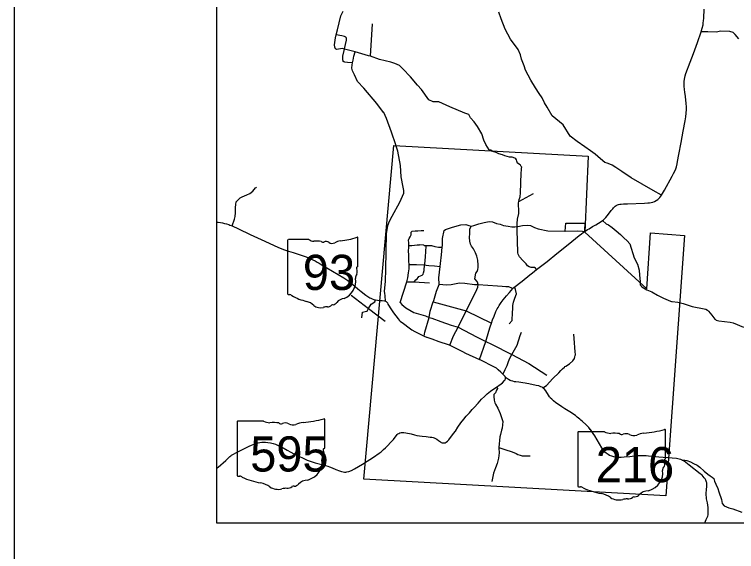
# Model space of a CAD drawing. Extents: x 2025369 to 2161369, y 549489 to 637489.
# Drawn here: x 2033369 to 2047673, y 570995 to 581630 of the extents above; entities that cross this region are included whole.
import ezdxf

# ---------------------------------------------------------------- set-up
doc = ezdxf.new("R2010")
doc.units = 0
for name, color, linetype in [('GM_X_City_Street', 7, 'Continuous'), ('GM_X_Corporation', 7, 'Continuous'), ('GM_X_County_Road', 7, 'Continuous'), ('GM_X_State_Route', 7, 'Continuous'), ('GM_X_State_Shield', 7, 'Continuous'), ('GM_X_Township_Road', 7, 'Continuous'), ('GM_X_Township_Subdivision', 7, 'Continuous'), ('SH_Border', 7, 'Continuous'), ('SH_Text', 7, 'Continuous')]:
    doc.layers.add(name, color=color, linetype=linetype)

msp = doc.modelspace()

# ---------------------------------------------------------------- linework, layer by layer
at = {"layer": 'GM_X_City_Street'}
for points in [[(2040772, 577465), (2040790, 577527), (2040851, 577634), (2041000, 577910), (2041058, 578035), (2041079, 578089), (2041079, 578141), (2041070, 578209), (2041026, 578413), (2041013, 578639), (2040960, 578922), (2040925, 579042), (2040923, 579047), (2040922, 579049)], [(2043343, 576907), (2043341, 576925), (2043327, 577359), (2043328, 577430), (2043328, 577489), (2043336, 577576), (2043358, 577688), (2043358, 577776), (2043356, 577842), (2043355, 577898), (2043360, 577926), (2043366, 577963), (2043383, 578017), (2043395, 578097), (2043404, 578490), (2043413, 578556), (2043414, 578586), (2043416, 578608), (2043409, 578622), (2043391, 578644), (2043373, 578658), (2043348, 578677), (2043332, 578685), (2043317, 578724), (2043313, 578750), (2043302, 578772), (2043278, 578782), (2043227, 578804), (2043173, 578807), (2043083, 578831), (2043036, 578852), (2042962, 578873), (2042914, 578896), (2042847, 578915)], [(2043360, 577926), (2043649, 578087)], [(2041878, 577355), (2041908, 577372), (2042043, 577421), (2042210, 577462), (2042311, 577469), (2042370, 577454), (2042418, 577437), (2042466, 577448), (2042569, 577484), (2042670, 577509), (2042770, 577531), (2042840, 577525), (2042918, 577494), (2042993, 577476), (2043059, 577453), (2043147, 577437), (2043222, 577427), (2043278, 577426), (2043328, 577430), (2043341, 577432), (2043431, 577450), (2043525, 577456), (2043593, 577453), (2043668, 577411), (2043746, 577385), (2043931, 577347), (2044273, 577336), (2044277, 577336), (2044520, 577345), (2044622, 577337), (2044663, 577332)], [(2044277, 577336), (2044293, 577497)], [(2044293, 577497), (2044675, 577499)], [(2044663, 577332), (2044664, 577357), (2044675, 577499)], [(2041178, 577002), (2041183, 577055), (2041180, 577107), (2041175, 577161), (2041178, 577181), (2041186, 577192), (2041207, 577226), (2041225, 577264), (2041228, 577298), (2041229, 577322), (2041247, 577337), (2041305, 577344), (2041359, 577347), (2041422, 577351), (2041476, 577350)], [(2041810, 576697), (2041831, 576871), (2041844, 577023), (2041847, 577052), (2041850, 577192), (2041878, 577355)], [(2042539, 576326), (2042534, 576343), (2042485, 576395), (2042510, 576506), (2042535, 576543), (2042549, 576581), (2042554, 576621), (2042551, 576667), (2042545, 576765), (2042529, 576843), (2042499, 576912), (2042460, 576991), (2042423, 577045), (2042404, 577080), (2042386, 577144), (2042383, 577212), (2042391, 577296), (2042392, 577338), (2042387, 577378), (2042418, 577437)], [(2041183, 577055), (2041243, 577056), (2041347, 577069), (2041380, 577071)], [(2041285, 576333), (2041293, 576343), (2041322, 576375), (2041347, 576398), (2041367, 576421), (2041382, 576439), (2041410, 576452), (2041446, 576470), (2041465, 576489), (2041471, 576513), (2041484, 576563), (2041494, 576674), (2041495, 576684), (2041514, 576830), (2041525, 577043), (2041525, 577057)], [(2041380, 577071), (2041389, 577071), (2041395, 577072), (2041469, 577069), (2041487, 577058), (2041519, 577057), (2041525, 577057), (2041583, 577056), (2041629, 577057), (2041697, 577035), (2041770, 577020), (2041844, 577023)], [(2041141, 576339), (2041161, 576412), (2041171, 576514), (2041185, 576593), (2041188, 576671), (2041187, 576681), (2041182, 576745), (2041178, 576851), (2041175, 576965), (2041178, 577002)], [(2043713, 576582), (2043689, 576607), (2043668, 576618), (2043637, 576618), (2043601, 576621), (2043564, 576635), (2043532, 576651), (2043503, 576691), (2043437, 576759), (2043373, 576834), (2043346, 576884), (2043343, 576907)], [(2041187, 576681), (2041331, 576680), (2041487, 576675), (2041494, 576674)], [(2041484, 575261), (2041499, 575338), (2041584, 575632), (2041601, 575755), (2041663, 575941), (2041673, 575969), (2041729, 576150), (2041780, 576284), (2041779, 576292), (2041777, 576414), (2041804, 576642), (2041810, 576697)], [(2041494, 576674), (2041521, 576669), (2041578, 576657), (2041688, 576650), (2041804, 576642)], [(2041008, 575926), (2041141, 576339)], [(2041141, 576339), (2041285, 576333), (2041591, 576319)], [(2041779, 576292), (2041852, 576281), (2041918, 576279), (2042021, 576283), (2042187, 576318), (2042293, 576307), (2042484, 576281), (2042553, 576280), (2042936, 576258), (2043028, 576251), (2043101, 576242), (2043157, 576241), (2043213, 576219), (2043241, 576202)], [(2041991, 575083), (2042068, 575265), (2042155, 575439), (2042319, 575764), (2042506, 576139), (2042546, 576228), (2042553, 576280), (2042539, 576326)], [(2043168, 575506), (2043227, 575569), (2043235, 575731), (2043239, 575799), (2043244, 575866), (2043256, 575935), (2043281, 576011), (2043311, 576101), (2043294, 576181), (2043284, 576202), (2043264, 576222)], [(2045780, 576257), (2045784, 576250), (2045793, 576236), (2045897, 576175), (2045996, 576135), (2046106, 576070), (2046223, 576013), (2046367, 575951), (2046387, 575949)], [(2040719, 575954), (2040710, 576060), (2040705, 576110)], [(2041008, 575926), (2041039, 575885), (2041122, 575824), (2041278, 575730), (2041510, 575662), (2041584, 575632), (2041636, 575614)], [(2041663, 575941), (2042319, 575764), (2042817, 575515)], [(2041636, 575614), (2041816, 575549), (2042018, 575475), (2042155, 575439), (2042521, 575248)], [(2043129, 574681), (2043146, 574741), (2043175, 574812), (2043224, 574900), (2043324, 575079), (2043387, 575272), (2043413, 575341)], [(2042521, 575248), (2042703, 575152)], [(2044479, 574898), (2044473, 574952), (2044453, 575212), (2044451, 575300)], [(2042703, 575152), (2042817, 575103), (2043224, 574900), (2043558, 574722), (2043915, 574489)], [(2044290, 574669), (2044362, 574714), (2044429, 574771), (2044464, 574818), (2044471, 574852), (2044478, 574879), (2044480, 574888), (2044479, 574898)], [(2043043, 574510), (2043076, 574570), (2043087, 574597), (2043124, 574665), (2043129, 574681)], [(2043837, 574240), (2043907, 574285), (2044033, 574420), (2044154, 574535), (2044193, 574580), (2044228, 574615), (2044262, 574648), (2044271, 574658), (2044290, 574669)], [(2042927, 574258), (2042936, 574224), (2042916, 574188), (2042895, 574135), (2042866, 574104), (2042863, 574086), (2042863, 574064), (2042871, 573996), (2042876, 573968), (2042887, 573937), (2042899, 573913), (2042942, 573835), (2042990, 573728), (2043040, 573573), (2043029, 573441), (2043017, 573397), (2042995, 573316)], [(2042995, 573316), (2042981, 573265), (2042966, 573054), (2042966, 573043), (2042970, 572953), (2042954, 572846), (2042932, 572742), (2042898, 572653), (2042857, 572548), (2042835, 572447), (2042826, 572381)], [(2042966, 573054), (2043084, 573019), (2043227, 572971), (2043304, 572936), (2043340, 572917), (2043383, 572902), (2043425, 572893), (2043493, 572888), (2043539, 572889), (2043585, 572892)]]:
    msp.add_lwpolyline(points, dxfattribs=at)
at = {"layer": 'GM_X_Corporation'}
msp.add_lwpolyline([(2044730, 578821), (2044666, 577321), (2045892, 576198), (2045966, 577309), (2046644, 577256), (2046273, 572097), (2040289, 572431), (2040884, 579034)], close=True, dxfattribs=at)
at = {"layer": 'GM_X_County_Road'}
for points in [[(2040686, 579686), (2040686, 579687), (2040682, 579691), (2040550, 579866), (2040292, 580173), (2040163, 580301), (2040102, 580437), (2040067, 580514), (2040052, 580564), (2040059, 580630), (2040068, 580671), (2040078, 580724), (2040091, 580803), (2040118, 580889), (2039908, 580945), (2039860, 580958), (2039752, 580933), (2039726, 580948), (2039712, 580980), (2039709, 581030), (2039728, 581164), (2039742, 581224), (2039766, 581327), (2039837, 581600), (2039877, 581697)], [(2047717, 581148), (2047648, 581236), (2047605, 581274), (2047542, 581292), (2047364, 581302), (2047268, 581282), (2047102, 581283), (2046973, 581288)], [(2040922, 579049), (2040838, 579301), (2040739, 579568), (2040686, 579686)], [(2040705, 576110), (2040702, 576145), (2040717, 576346), (2040724, 576586), (2040741, 577295), (2040765, 577443), (2040768, 577453), (2040772, 577465)], [(2045018, 577549), (2045092, 577484), (2045134, 577467), (2045211, 577412), (2045289, 577346), (2045374, 577272), (2045441, 577205), (2045505, 577149), (2045560, 577089), (2045646, 576813), (2045712, 576683), (2045741, 576568), (2045752, 576470), (2045762, 576340), (2045766, 576278), (2045780, 576257)], [(2046387, 575949), (2046394, 575948), (2046510, 575933), (2046612, 575910), (2046794, 575848), (2047031, 575803), (2047065, 575792), (2047095, 575775), (2047117, 575752), (2047186, 575675), (2047242, 575599), (2047255, 575587), (2047271, 575576), (2047323, 575562), (2047545, 575535), (2047606, 575523), (2047810, 575441)]]:
    msp.add_lwpolyline(points, dxfattribs=at)
at = {"layer": 'GM_X_State_Route'}
for points in [[(2044663, 577332), (2044693, 577353), (2044720, 577370), (2044752, 577388), (2044822, 577429), (2044886, 577466), (2044935, 577495), (2044992, 577530), (2045018, 577549), (2045039, 577566), (2045059, 577585), (2045084, 577612), (2045133, 577673), (2045192, 577750), (2045219, 577784), (2045234, 577801), (2045248, 577815), (2045268, 577831), (2045290, 577845), (2045314, 577858), (2045336, 577867), (2045359, 577871), (2045390, 577876), (2045430, 577879), (2045512, 577882), (2045850, 577895), (2045916, 577897), (2045949, 577900), (2045982, 577905), (2046015, 577912), (2046050, 577926), (2046083, 577944), (2046115, 577967), (2046150, 578004), (2046171, 578032), (2046185, 578053), (2046242, 578151), (2046397, 578425), (2046425, 578478), (2046449, 578524), (2046468, 578572), (2046482, 578615), (2046496, 578671), (2046505, 578716), (2046532, 578860), (2046575, 579095), (2046616, 579316), (2046655, 579527), (2046667, 579605), (2046676, 579675), (2046681, 579750), (2046679, 579803), (2046675, 579869), (2046661, 580003), (2046649, 580090), (2046643, 580144), (2046636, 580211), (2046633, 580255), (2046634, 580301), (2046640, 580348), (2046646, 580382), (2046655, 580415), (2046669, 580460), (2046753, 580683), (2046819, 580860), (2046896, 581074), (2046973, 581288), (2046993, 581359), (2047008, 581423), (2047014, 581464), (2047019, 581505), (2047023, 581558), (2047031, 581736)], [(2037369, 577517), (2037403, 577515), (2037449, 577510), (2037491, 577504), (2037531, 577493), (2037572, 577482), (2037615, 577468), (2037635, 577461), (2037679, 577444), (2037805, 577383), (2038037, 577271), (2038256, 577171), (2038588, 577022), (2038701, 576978), (2038798, 576943), (2038888, 576915), (2038969, 576889), (2039148, 576828), (2039192, 576811), (2039238, 576793), (2039280, 576774), (2039327, 576749), (2039365, 576728), (2039407, 576704), (2039446, 576681), (2039894, 576415), (2039970, 576364), (2039999, 576345), (2040021, 576329), (2040173, 576199)], [(2043632, 576516), (2043713, 576582), (2043918, 576740), (2044115, 576899), (2044338, 577077), (2044558, 577254), (2044604, 577289), (2044634, 577312), (2044663, 577332)], [(2042956, 575843), (2042972, 575870), (2043009, 575926), (2043047, 575979), (2043115, 576061), (2043173, 576126), (2043241, 576202), (2043264, 576222), (2043423, 576347), (2043580, 576474), (2043632, 576516)], [(2040173, 576199), (2040238, 576144), (2040331, 576072), (2040366, 576047), (2040387, 576033), (2040408, 576021), (2040430, 576011), (2040457, 576000), (2040487, 575989), (2040521, 575980), (2040560, 575971), (2040598, 575967), (2040652, 575964), (2040653, 575964)], [(2040653, 575964), (2040701, 575960), (2040719, 575954), (2040733, 575945), (2040744, 575934), (2040755, 575918), (2040767, 575896), (2040778, 575874), (2040822, 575798), (2040848, 575759), (2040876, 575722), (2040969, 575603), (2040989, 575580), (2041009, 575560), (2041073, 575508), (2041190, 575422), (2041241, 575387), (2041301, 575354), (2041354, 575327), (2041484, 575261), (2041533, 575240)], [(2042869, 575659), (2042904, 575746), (2042931, 575801), (2042948, 575830), (2042956, 575843)], [(2042768, 575360), (2042793, 575442), (2042817, 575515), (2042840, 575584), (2042869, 575659), (2042869, 575659)], [(2042578, 574797), (2042703, 575152), (2042768, 575360)], [(2041533, 575240), (2041540, 575237), (2041634, 575205), (2041773, 575157), (2041962, 575095), (2041991, 575083)], [(2041991, 575083), (2042083, 575037), (2042243, 574956), (2042306, 574926)], [(2042306, 574926), (2042578, 574797)], [(2043004, 574549), (2043003, 574550), (2042953, 574595), (2042932, 574613), (2042915, 574626), (2042888, 574642), (2042578, 574797)], [(2044588, 573599), (2044567, 573616), (2044515, 573659), (2044480, 573687), (2044448, 573709), (2044420, 573729), (2044373, 573760), (2044272, 573823), (2044209, 573862), (2044146, 573904), (2044093, 573941), (2044045, 573982), (2044015, 574010), (2043983, 574040), (2043973, 574051), (2043965, 574061), (2043946, 574095), (2043928, 574127), (2043915, 574145), (2043893, 574178), (2043870, 574208), (2043851, 574227), (2043837, 574240), (2043820, 574250), (2043798, 574260), (2043782, 574265), (2043755, 574274), (2043704, 574284), (2043555, 574317), (2043519, 574325), (2043488, 574330), (2043436, 574339), (2043362, 574347), (2043302, 574355), (2043276, 574359), (2043239, 574367), (2043205, 574376), (2043187, 574383), (2043154, 574401), (2043094, 574441), (2043092, 574453), (2043087, 574462), (2043072, 574481), (2043049, 574504), (2043043, 574510), (2043004, 574549)], [(2040590, 572942), (2040632, 572973), (2040681, 573014), (2040720, 573051), (2040764, 573094), (2040821, 573153), (2040875, 573211), (2040911, 573257), (2040937, 573292), (2040950, 573310), (2040965, 573324), (2040980, 573336), (2041004, 573347), (2041028, 573352), (2041048, 573353), (2041082, 573350), (2041123, 573343), (2041224, 573323), (2041295, 573305), (2041342, 573294), (2041389, 573286), (2041446, 573278), (2041523, 573271), (2041604, 573262), (2041636, 573258), (2041664, 573253), (2041682, 573247), (2041706, 573235), (2041734, 573219), (2041768, 573192), (2041805, 573165), (2041823, 573155), (2041843, 573148), (2041859, 573146), (2041882, 573148), (2041900, 573151), (2041920, 573161), (2041944, 573178), (2041974, 573208), (2042067, 573331), (2042103, 573379), (2042154, 573458), (2042213, 573544), (2042270, 573619), (2042319, 573674), (2042380, 573740), (2042438, 573805), (2042477, 573848), (2042554, 573936), (2042618, 574012), (2042677, 574068), (2042730, 574117), (2042800, 574172), (2042927, 574258), (2042965, 574284), (2043011, 574318), (2043033, 574338), (2043077, 574380), (2043086, 574393), (2043090, 574403), (2043093, 574416), (2043094, 574429), (2043094, 574441)], [(2044775, 573415), (2044744, 573452), (2044688, 573510), (2044624, 573568), (2044588, 573599)], [(2046076, 572870), (2045931, 572885), (2045879, 572889), (2045831, 572892), (2045781, 572893), (2045737, 572891), (2045690, 572888), (2045560, 572874), (2045449, 572863), (2045390, 572858), (2045335, 572856), (2045280, 572861), (2045241, 572870), (2045202, 572883), (2045157, 572899), (2045127, 572917), (2045090, 572942), (2045065, 572963), (2045040, 572994), (2045004, 573046), (2044864, 573286), (2044862, 573287), (2044835, 573332), (2044808, 573373), (2044780, 573410), (2044775, 573415)], [(2037369, 572632), (2037406, 572663), (2037555, 572797), (2037612, 572853), (2037636, 572876), (2037653, 572891), (2037667, 572903), (2037693, 572919), (2037765, 572959), (2038020, 573085), (2038066, 573105), (2038100, 573118), (2038148, 573134), (2038198, 573149), (2038229, 573156), (2038266, 573161), (2038303, 573163), (2038343, 573161), (2038385, 573156), (2038442, 573147), (2038492, 573135), (2038538, 573121), (2038593, 573098), (2038660, 573066), (2038768, 573003), (2038842, 572961), (2038902, 572931), (2038986, 572891), (2039101, 572839), (2039170, 572807), (2039226, 572787), (2039324, 572755), (2039533, 572697), (2039576, 572684), (2039612, 572671), (2039665, 572652), (2039733, 572623), (2039810, 572591), (2039845, 572578), (2039880, 572571), (2039908, 572568), (2039935, 572570), (2039956, 572573), (2039992, 572582), (2040042, 572602), (2040105, 572634), (2040261, 572724), (2040357, 572783), (2040410, 572817), (2040481, 572863), (2040590, 572942)], [(2047042, 571561), (2047073, 571627), (2047092, 571667), (2047103, 571697), (2047109, 571723), (2047113, 571760), (2047113, 571804), (2047107, 571865), (2047094, 571958), (2047079, 572037), (2047075, 572077), (2047072, 572105), (2047070, 572143), (2047077, 572225), (2047083, 572284), (2047083, 572324), (2047081, 572354), (2047078, 572372), (2047073, 572390), (2047063, 572411), (2047050, 572435), (2047034, 572457), (2047013, 572483), (2046990, 572506), (2046954, 572536), (2046734, 572708), (2046632, 572785), (2046596, 572806), (2046572, 572817), (2046538, 572826), (2046512, 572832), (2046482, 572836), (2046400, 572847), (2046136, 572864), (2046076, 572870)]]:
    msp.add_lwpolyline(points, dxfattribs=at)
at = {"layer": 'GM_X_State_Shield'}
for p, q in [((2039202, 577175), (2038794, 577175)), ((2040172, 576648), (2040172, 577201)), ((2038780, 577157), (2038780, 576100)), ((2040172, 576649), (2040172, 576648)), ((2039519, 573054), (2039519, 573606)), ((2039519, 573606), (2039519, 573606)), ((2037796, 573580), (2037796, 573580)), ((2044528, 573351), (2044528, 572294)), ((2045055, 573369), (2044545, 573369)), ((2046268, 572842), (2046268, 573395)), ((2046268, 572843), (2046268, 572842)), ((2037779, 572505), (2037778, 572505))]:
    msp.add_line(p, q, dxfattribs=at)
for points in [[(2037778, 573562), (2037779, 573562), (2037779, 572505)], [(2038305, 573580), (2038305, 573580), (2037796, 573580)], [(2039519, 573054), (2039519, 573054), (2039519, 573054)]]:
    msp.add_lwpolyline(points, dxfattribs=at)
for centre, radius, start, end in [((2038796, 577159), 16.1, 98.1301, 188.1301), ((2039299, 577298), 156, 231.6195, 271.1119), ((2039677, 578616), 1476, 275.8445, 288.9065), ((2040157, 577203), 15.5, 351.8621, 97.738), ((2039351, 576582), 562, 80.4867, 94.9883), ((2039478, 577164), 45.1, 219.7921, 297.1024), ((2039544, 577042), 93.8, 54.4667, 119.1411), ((2039665, 577210), 113, 233.8562, 294.8282), ((2039865, 576852), 297, 97.3462, 120.7689), ((2040169, 576608), 24, 107.944, 210.337), ((2040016, 576538), 144, 340.033, 23.6496), ((2040156, 576646), 16.6, 289.6038, 7.7341), ((2040228, 576417), 105, 136.8065, 186.9296), ((2039759, 576347), 369, 292.3089, 8.9858), ((2038796, 576098), 16.3, 171.9584, 258.3066), ((2038799, 576206), 124, 267.339, 280.6039), ((2038824, 576039), 44.8, 29.7484, 93.2717), ((2039390, 576989), 1066, 240.4129, 257.1985), ((2039072, 575625), 334, 47.1842, 75.836), ((2039570, 575955), 113, 268.777, 315.5493), ((2039672, 575852), 31.8, 65.7517, 132.6484), ((2039659, 575998), 119, 282.8732, 323.2771), ((2039915, 575803), 202, 94.4031, 142.5768), ((2039432, 576034), 212, 230.7004, 286.2918), ((2039555, 575669), 174, 85.6951, 111.2099)]:
    msp.add_arc(centre, radius, start, end, dxfattribs=at)
for centre, major_axis, start_param, end_param in [((2038899, 575021), (1845, 0), 4.814394, 5.042369), ((2039499, 573609), (19.4, 0), 6.141152, 7.989035), ((2037798, 573564), (20.2, 0), 1.712693, 3.28349), ((2038427, 573703), (196, 0), 4.042523, 4.731795), ((2038491, 572987), (702, 0), 1.404758, 1.657858), ((2038651, 573570), (56.4, 0), 3.836095, 5.185415), ((2038734, 573448), (117, 0), 0.950623, 2.079405), ((2038885, 573615), (141, 0), 4.081561, 5.145723), ((2039134, 573257), (371, 0), 1.699011, 2.107814), ((2044548, 573353), (20.2, 0), 1.712693, 3.28349), ((2045176, 573492), (196, 0), 4.042523, 4.731795), ((2045241, 572776), (702, 0), 1.404758, 1.657858), ((2045400, 573359), (56.4, 0), 3.836095, 5.185415), ((2045483, 573236), (117, 0), 0.950623, 2.079405), ((2045635, 573404), (141, 0), 4.081561, 5.145723), ((2045884, 573046), (371, 0), 1.699011, 2.107814), ((2045648, 574810), (1845, 0), 4.814394, 5.042369), ((2046249, 573397), (19.4, 0), 6.141152, 7.989035), ((2039514, 573013), (30, 0), 1.883978, 3.671073), ((2039498, 573051), (20.7, 0), 5.05454, 6.418171), ((2039588, 572822), (131, 0), 2.387724, 3.262537), ((2039324, 572943), (180, 0), 5.934695, 6.695948), ((2039002, 572752), (462, 0), 5.101752, 6.440018), ((2046264, 572802), (30, 0), 1.883978, 3.671073), ((2046073, 572732), (180, 0), 5.934695, 6.695948), ((2046248, 572840), (20.7, 0), 5.05454, 6.418171), ((2045752, 572541), (462, 0), 5.101752, 6.440018), ((2046338, 572611), (131, 0), 2.387724, 3.262537), ((2037799, 572503), (20.3, 0), 3.00124, 4.508301), ((2037802, 572611), (155, 0), 4.665946, 4.897461), ((2037833, 572444), (56, 0), 0.519207, 1.627899), ((2038540, 573394), (1333, 0), 4.195997, 4.488961), ((2038143, 572031), (417, 0), 0.823519, 1.323587), ((2038877, 572403), (149, 0), 4.937069, 5.64225), ((2039197, 572209), (253, 0), 1.647645, 2.488434), ((2038594, 572439), (265, 0), 4.026481, 4.996735), ((2038747, 572074), (217, 0), 1.495662, 1.94098), ((2038766, 572360), (141, 0), 4.691044, 5.507374), ((2038893, 572258), (39.7, 0), 1.147584, 2.315152), ((2044548, 572292), (20.3, 0), 3.00124, 4.508301), ((2044551, 572400), (155, 0), 4.665946, 4.897461), ((2044583, 572233), (56, 0), 0.519207, 1.627899), ((2045290, 573183), (1333, 0), 4.195997, 4.488961), ((2045946, 571997), (253, 0), 1.647645, 2.488434), ((2044892, 571819), (417, 0), 0.823519, 1.323587), ((2045343, 572228), (265, 0), 4.026481, 4.996735), ((2045496, 571863), (217, 0), 1.495662, 1.94098), ((2045516, 572149), (141, 0), 4.691044, 5.507374), ((2045643, 572046), (39.7, 0), 1.147584, 2.315152), ((2045626, 572192), (149, 0), 4.937069, 5.64225)]:
    msp.add_ellipse(centre, major_axis=major_axis, ratio=0.8, start_param=start_param, end_param=end_param, dxfattribs=at)
at = {"layer": 'GM_X_Township_Road'}
for points in [[(2046185, 578053), (2046021, 578142), (2045806, 578269), (2045588, 578398), (2045401, 578519), (2045280, 578598), (2045207, 578646), (2045161, 578667), (2045112, 578683), (2045060, 578700), (2044979, 578772), (2044875, 578865), (2044778, 578932), (2044666, 579006), (2044517, 579114), (2044379, 579219), (2044238, 579442), (2044022, 579626), (2043924, 579797), (2043871, 579883), (2043820, 579977), (2043765, 580064), (2043690, 580177), (2043598, 580331), (2043494, 580530), (2043465, 580612), (2043411, 580747), (2043391, 580831), (2043347, 580939), (2043193, 581141), (2043091, 581338), (2043009, 581545), (2042961, 581678)], [(2042847, 578915), (2042802, 578943), (2042772, 578951), (2042736, 579000), (2042703, 579052), (2042668, 579143), (2042627, 579267), (2042543, 579410), (2042472, 579503), (2042405, 579580), (2042367, 579646), (2042290, 579677), (2041995, 579803), (2041772, 579899), (2041666, 579901), (2041580, 579940), (2041430, 580145), (2041355, 580230), (2041217, 580398), (2041061, 580556), (2040995, 580622), (2040902, 580657), (2040822, 580684), (2040600, 580741), (2040424, 580801), (2040385, 580814), (2040118, 580889)], [(2037679, 577444), (2037728, 577574), (2037739, 577628), (2037750, 577702), (2037746, 577807), (2037754, 577870), (2037759, 577920), (2037791, 577954), (2037843, 578000), (2037879, 578020), (2037975, 578056), (2038031, 578087), (2038089, 578131), (2038144, 578195), (2038154, 578203), (2038162, 578210)], [(2040253, 575625), (2040262, 575734), (2040342, 575752), (2040357, 575757), (2040383, 575807), (2040438, 575891), (2040507, 575941), (2040521, 575980)], [(2046596, 572806), (2046651, 572804), (2046688, 572798), (2046760, 572773), (2046822, 572742), (2046890, 572705), (2046948, 572663), (2047034, 572585), (2047104, 572525), (2047149, 572493), (2047191, 572467), (2047224, 572444), (2047233, 572386), (2047262, 572330), (2047299, 572242), (2047322, 572177), (2047371, 572025), (2047390, 571947), (2047429, 571900), (2047517, 571859), (2047599, 571842), (2047776, 571776)]]:
    msp.add_lwpolyline(points, dxfattribs=at)
at = {"layer": 'GM_X_Township_Subdivision'}
for points in [[(2040424, 580801), (2040464, 581446)], [(2040068, 580671), (2039968, 580681), (2039915, 580684), (2039901, 580689), (2039893, 580692), (2039882, 580700), (2039879, 580714), (2039876, 580731), (2039873, 580758), (2039876, 580803), (2039908, 580945), (2039909, 580949), (2039943, 581118), (2039945, 581152), (2039940, 581171), (2039932, 581182), (2039907, 581196), (2039882, 581202), (2039851, 581210), (2039742, 581224)], [(2040040, 576071), (2040383, 575807), (2040709, 575556)]]:
    msp.add_lwpolyline(points, dxfattribs=at)
at = {"layer": 'SH_Border'}
msp.add_lwpolyline([(2033369, 635489), (2159369, 635489), (2159369, 551489), (2033369, 551489)], close=True, dxfattribs=at)
at = {"layer": 'SH_Text'}
msp.add_lwpolyline([(2037369, 631489), (2037369, 571561), (2092420, 571561), (2092420, 631489)], dxfattribs=at)

# ---------------------------------------------------------------- texts
at = {"layer": 'GM_X_State_Shield'}
for s, p in [('93', (2039081, 576175)), ('595', (2038038, 572580)), ('216', (2044884, 572369))]:
    msp.add_text(s, height=696.1, dxfattribs=at).set_placement(p)

doc.saveas('drawing.dxf')
